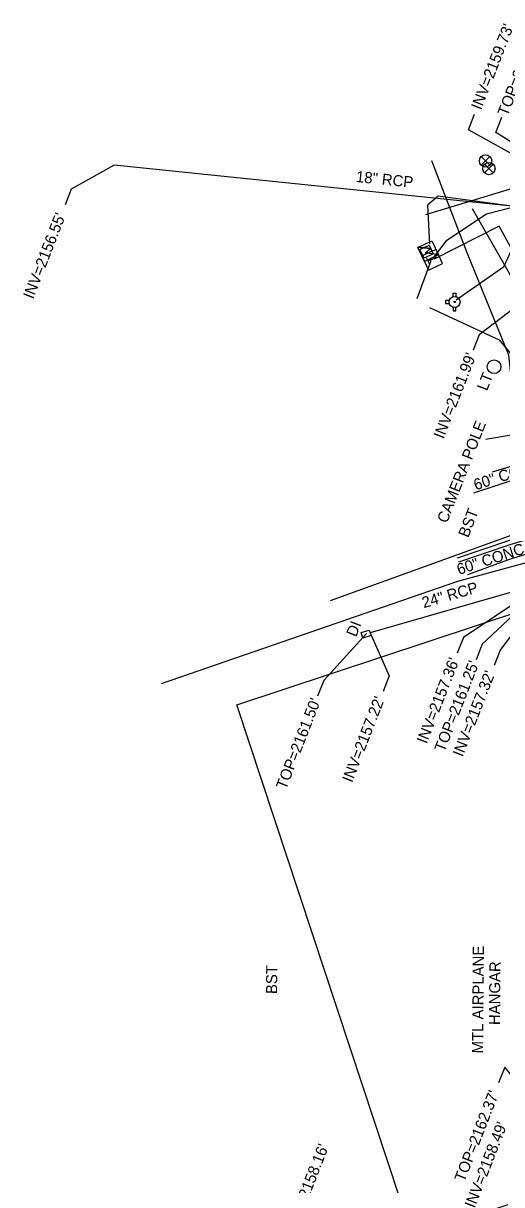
# Model space of a CAD drawing. Extents: x 945964 to 948456, y 631061 to 636061.
# Drawn here: x 946200.3 to 946372.2, y 633199.7 to 633616.6 of the extents above; entities that cross this region are included whole.
import ezdxf

# ---------------------------------------------------------------- set-up
doc = ezdxf.new("R2010")
doc.units = 0
for name, color, linetype in [('Exist Building', 7, 'Continuous'), ('Exist Building Text', 7, 'Continuous'), ('Exist Roads Curbs', 7, 'Continuous'), ('Exist Roads EOP', 7, 'Continuous'), ('Exist Roads EOP Other', 7, 'Continuous'), ('Exist Roads EOP Other Text', 7, 'Continuous'), ('Exist Roads EOP Text', 7, 'Continuous'), ('Exist Structure Minor Catch Basin Top Elevation', 7, 'Continuous'), ('Exist Structure Minor Drop Inlet', 7, 'Continuous'), ('Exist Structure Minor Drop Inlet Text', 7, 'Continuous'), ('Exist Structure Minor Drop Inlet Top Elevation', 7, 'Continuous'), ('Exist Structure Minor Pipes RCP 18 Inch', 7, 'Continuous'), ('Exist Structure Minor Pipes RCP 18 Inch Invert', 7, 'Continuous'), ('Exist Structure Minor Pipes RCP 18 Inch Text', 7, 'Continuous'), ('Exist Structure Minor Pipes RCP 24 Inch', 7, 'Continuous'), ('Exist Structure Minor Pipes RCP 24 Inch Invert', 7, 'Continuous'), ('Exist Structure Minor Pipes RCP 24 Inch Text', 7, 'Continuous'), ('Exist Utilities Gas UG Line SUE', 7, 'Continuous'), ('Exist Utilities Other Located Object Leader', 7, 'Continuous'), ('Exist Utilities Other Located Object Text', 7, 'Continuous'), ('Exist Utilities Other Pole CELL', 7, 'Continuous'), ('Exist Utilities Other Pole Text', 7, 'Continuous'), ('Exist Utilities Power Transformer CELL', 7, 'Continuous'), ('Exist Utilities Power UG Cable SUE', 7, 'Continuous'), ('Exist Utilities Telephone Pedestal CELL', 7, 'Continuous'), ('Exist Utilities Telephone UG Cable SUE', 7, 'Continuous'), ('Exist Utilities Telephone UG FO SUE', 7, 'Continuous'), ('Exist Utilities Water Fire Hydrant CELL', 7, 'Continuous'), ('Exist Utilities Water UG Line SUE', 7, 'Continuous'), ('Exist Utilities Water Valve CELL', 7, 'Continuous')]:
    doc.layers.add(name, color=color, linetype=linetype)

# ---------------------------------------------------------------- blocks, each defined once
blk = doc.blocks.new('EXIST UTILITIES TELEPHONE PEDESTAL')
at = {"layer": 'Exist Utilities Telephone Pedestal CELL'}
blk.add_line((0, 0), (0, 0), dxfattribs=at)
blk.add_lwpolyline([(-0.0545, -0.0565), (0.0574, -0.0565), (0.0574, 0.0554), (-0.0545, 0.0554), (-0.0545, -0.0565)], dxfattribs=at)
blk.add_text('T', height=0.0684, dxfattribs=at).set_placement((-0.0226, -0.0343))
blk = doc.blocks.new('EXIST UTILITIES POWER TRANSFORMER')
at = {"layer": 'Exist Utilities Power Transformer CELL'}
blk.add_line((0, 0), (0, 0), dxfattribs=at)
blk.add_lwpolyline([(-0.0569, 0.0522), (0.0542, 0.0522), (0.0542, -0.0588), (-0.0569, -0.0588)], close=True, dxfattribs=at)
for points in [[(-0.0569, -0.0588), (-0.004, 0.0201), (0.0086, -0.0241), (0.0542, 0.0522)], [(-0.0555, -0.0588), (-0.004, 0.0159), (0.0077, -0.0278), (0.0542, 0.0491)]]:
    blk.add_lwpolyline(points, dxfattribs=at)
blk = doc.blocks.new('EXIST UTILITIES WATER VALVE')
at = {"layer": 'Exist Utilities Water Valve CELL'}
blk.add_lwpolyline([(0.0315, 0.0315), (-0.0315, -0.0315), (0, 0), (0.0315, -0.0315), (-0.0315, 0.0315)], dxfattribs=at)
blk.add_circle((0, 0), 0.0445, dxfattribs=at)
blk = doc.blocks.new('EXIST UTILITIES WATER FIRE HYDRANT')
at = {"layer": 'Exist Utilities Water Fire Hydrant CELL'}
blk.add_line((0, 0), (0, 0), dxfattribs=at)
for points in [[(-0.0382, 0.0103), (-0.064, 0.0103), (-0.064, -0.0103), (-0.0382, -0.0103)], [(-0.0103, 0.0382), (-0.0103, 0.064), (0.0103, 0.064), (0.0103, 0.0377)], [(-0.0103, -0.0382), (-0.0103, -0.064), (0.0103, -0.064), (0.0103, -0.0377)]]:
    blk.add_lwpolyline(points, dxfattribs=at)
for radius in [0.0395, 0.00485]:
    blk.add_circle((0, 0), radius, dxfattribs=at)
blk = doc.blocks.new('EXIST UTILITIES OTHER POLE')
at = {"layer": 'Exist Utilities Other Pole CELL'}
blk.add_circle((0, 0), 0.0493, dxfattribs=at)

msp = doc.modelspace()

# ---------------------------------------------------------------- linework, layer by layer
at = {"layer": 'Exist Building'}
msp.add_lwpolyline([(946443.69, 633215.47), (946340.12, 633181.14), (946277.06, 633372.05), (946380.49, 633406.21)], close=True, dxfattribs=at)
at = {"layer": 'Exist Roads Curbs'}
msp.add_lwpolyline([(946356.79, 633423.33), (946375.2, 633429.5), (946385.96, 633432.76), (946390.43, 633433.32), (946393.92, 633433.06), (946397.24, 633432.41), (946398.56, 633432.01)], dxfattribs=at)
at = {"layer": 'Exist Roads EOP'}
for points in [[(946395.61, 633473.47), (946397.09, 633469.17), (946397.19, 633466.43), (946396.51, 633463.92), (946395.02, 633461.81), (946393.17, 633459.77), (946390.62, 633457.89), (946388.03, 633456.47), (946378.82, 633453.47), (946361.95, 633447.99)], [(946356.32, 633424.75), (946374.75, 633430.93), (946385.65, 633434.23), (946390.39, 633434.82), (946394.12, 633434.55), (946397.6, 633433.87), (946402.55, 633432.35), (946408.59, 633429.59), (946414.48, 633425.92), (946418.03, 633423.03), (946423.58, 633417.87), (946427.76, 633412.39), (946431.85, 633405.16), (946434.62, 633399.21), (946437.11, 633392.39), (946440.04, 633382.71), (946444.03, 633370.06), (946449.76, 633351.25), (946456.69, 633328.4), (946462.97, 633307.72), (946467.95, 633291.29)]]:
    msp.add_lwpolyline(points, dxfattribs=at)
at = {"layer": 'Exist Roads EOP Other'}
for points in [[(946344.29, 633532.36), (946342.79, 633535.37), (946346.05, 633536.99), (946347.51, 633533.84), (946344.29, 633532.36)], [(946386.37, 633475.81), (946389.06, 633470.96), (946390.23, 633467.47), (946390.32, 633466.02), (946389.67, 633464.07), (946388.41, 633462.88), (946387.03, 633461.51), (946385.91, 633460.99), (946381.78, 633459.62), (946373.82, 633457), (946368.7, 633455.45)], [(946397.66, 633421.53), (946395.55, 633426.42), (946391.11, 633426.9), (946386.38, 633426.81), (946380.86, 633425.91), (946375.58, 633424.35), (946359.88, 633418.66)]]:
    msp.add_lwpolyline(points, dxfattribs=at)
at = {"layer": 'Exist Structure Minor Catch Basin Top Elevation'}
msp.add_lwpolyline([(946411.5, 633195.51), (946373.23, 633241.96), (946371.04, 633236.37)], dxfattribs=at)
at = {"layer": 'Exist Structure Minor Drop Inlet'}
msp.add_lwpolyline([(946324.59, 633398.78), (946325.26, 633396.85), (946322.31, 633395.97), (946321.7, 633398.01), (946324.59, 633398.78)], dxfattribs=at)
at = {"layer": 'Exist Structure Minor Drop Inlet Top Elevation'}
for points in [[(946418.35, 633547.12), (946370.03, 633577.37), (946372.21, 633582.95)], [(946389.17, 633416.22), (946365.15, 633393.74), (946362.97, 633388.16)], [(946323.63, 633397.55), (946308.22, 633380.71), (946306.03, 633375.12)]]:
    msp.add_lwpolyline(points, dxfattribs=at)
at = {"layer": 'Exist Structure Minor Pipes RCP 18 Inch'}
msp.add_line((946417.02, 633546.75), (946232.99, 633565.65), dxfattribs=at)
msp.add_line((946417.02, 633546.75), (946232.99, 633565.65), dxfattribs=at)
at = {"layer": 'Exist Structure Minor Pipes RCP 18 Inch Invert'}
for points in [[(946417.02, 633546.75), (946360.22, 633578.39), (946362.41, 633583.98)], [(946232.99, 633565.65), (946217.51, 633557.05), (946215.32, 633551.47)], [(946418.32, 633546.11), (946364.04, 633504.84), (946361.85, 633499.25)]]:
    msp.add_lwpolyline(points, dxfattribs=at)
at = {"layer": 'Exist Structure Minor Pipes RCP 24 Inch'}
msp.add_line((946387.98, 633415.96), (946324.86, 633397.79), dxfattribs=at)
at = {"layer": 'Exist Structure Minor Pipes RCP 24 Inch Invert'}
for points in [[(946387.98, 633415.96), (946358.38, 633396.16), (946356.19, 633390.57)], [(946389.55, 633415.66), (946371.57, 633391.67), (946369.38, 633386.08)], [(946324.86, 633397.79), (946331.78, 633382.43), (946329.6, 633376.84)]]:
    msp.add_lwpolyline(points, dxfattribs=at)
at = {"layer": 'Exist Utilities Gas UG Line SUE'}
msp.add_line((946310.62, 633409.44), (946417.38, 633448.02), dxfattribs=at)
for points in [[(946619.67, 632824.44), (946594.97, 632905.61), (946571.92, 632968.94), (946532.75, 633083.03), (946501.7, 633172.99), (946488.79, 633216.05), (946469.59, 633278.14), (946458.18, 633325.93), (946447.15, 633359.21), (946427.01, 633420.51), (946410.77, 633466.26), (946393.83, 633493.79), (946361.71, 633549.95)], [(946346.24, 633514.61), (946371.27, 633503.04), (946385.56, 633485.67), (946410.45, 633466.34)]]:
    msp.add_lwpolyline(points, dxfattribs=at)
at = {"layer": 'Exist Utilities Other Located Object Leader'}
msp.add_lwpolyline([(946381.08, 633469.74), (946366.41, 633467.27)], dxfattribs=at)
at = {"layer": 'Exist Utilities Power UG Cable SUE'}
msp.add_lwpolyline([(946485.31, 633431.45), (946479.38, 633442.7), (946463.36, 633488.11), (946452.17, 633505.48), (946414.56, 633545.7), (946349.36, 633554.61), (946345.45, 633551.29), (946346.17, 633537.3)], dxfattribs=at)
at = {"layer": 'Exist Utilities Telephone UG Cable SUE'}
msp.add_line((946346.7, 633531.33), (946341.66, 633517.76), dxfattribs=at)
for points in [[(946416.51, 633555.47), (946393.78, 633548.5), (946375.09, 633550.21), (946366.73, 633548.12), (946352.03, 633538.41), (946347.53, 633532.4)], [(946468.58, 633229.29), (946480.21, 633232.87), (946453.77, 633319.31), (946426.75, 633410.6), (946402.77, 633464), (946403.53, 633475.93), (946397.38, 633496.17), (946371.22, 633543.74), (946347.87, 633531.98)]]:
    msp.add_lwpolyline(points, dxfattribs=at)
at = {"layer": 'Exist Utilities Telephone UG FO SUE'}
msp.add_line((946405.56, 633566.23), (946344.81, 633547.82), dxfattribs=at)
for points in [[(946471.38, 633227.98), (946453.83, 633274.93), (946421.19, 633376.74), (946415.16, 633410.84), (946396.18, 633428.86), (946375.84, 633486.53), (946374.65, 633497.52), (946359.69, 633534.21), (946347.03, 633567.22)], [(946249.92, 633379.71), (946356.43, 633416.36), (946396.06, 633427.15)]]:
    msp.add_lwpolyline(points, dxfattribs=at)
at = {"layer": 'Exist Utilities Water UG Line SUE'}
msp.add_lwpolyline([(946380.27, 633543), (946378.58, 633541.55), (946372.81, 633529.03), (946355.76, 633517.27)], dxfattribs=at)

# ---------------------------------------------------------------- block references
at = {"layer": 'Exist Utilities Other Pole CELL', "xscale": 50, "yscale": 50}
msp.add_blockref('EXIST UTILITIES OTHER POLE', (946369.38, 633493.33), dxfattribs=at)
at = {"layer": 'Exist Utilities Power Transformer CELL', "xscale": 49.99999999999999, "yscale": 49.999999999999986, "rotation": 115.10487278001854}
msp.add_blockref('EXIST UTILITIES POWER TRANSFORMER', (946345.53, 633534.78), dxfattribs=at)
at = {"layer": 'Exist Utilities Telephone Pedestal CELL', "xscale": 49.99999999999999, "yscale": 49.99999999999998, "rotation": 114.83996844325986}
msp.add_blockref('EXIST UTILITIES TELEPHONE PEDESTAL', (946347.19, 633531.66), dxfattribs=at)
at = {"layer": 'Exist Utilities Water Fire Hydrant CELL', "xscale": 50, "yscale": 50}
msp.add_blockref('EXIST UTILITIES WATER FIRE HYDRANT', (946355.2, 633516.59), dxfattribs=at)
at = {"layer": 'Exist Utilities Water Valve CELL', "xscale": 50, "yscale": 50}
for p in [(946366.35, 633567.2), (946367.55, 633564.46)]:
    msp.add_blockref('EXIST UTILITIES WATER VALVE', p, dxfattribs=at)

# ---------------------------------------------------------------- texts
at = {"layer": 'Exist Building Text'}
for s, p in [('MTL AIRPLANE', (946365.45, 633246.88)), ('HANGAR', (946371.53, 633257.05))]:
    msp.add_text(s, height=4, rotation=89.5187, dxfattribs=at).set_placement(p)
at = {"layer": 'Exist Roads EOP Other Text'}
for rotation, p in [(68.935, (946360.13, 633431.75)), (89.5187, (946291.48, 633268.18))]:
    msp.add_text('BST', height=4, rotation=rotation, dxfattribs=at).set_placement(p)
at = {"layer": 'Exist Roads EOP Text'}
for p in [(946362.82, 633448.95), (946356.78, 633418.58)]:
    msp.add_text('60" CONC', height=4, rotation=18.0277, dxfattribs=at).set_placement(p)
at = {"layer": 'Exist Structure Minor Catch Basin Top Elevation'}
msp.add_text("TOP=2162.37'", height=4, rotation=68.6189, dxfattribs=at).set_placement((946358.74, 633200.5))
at = {"layer": 'Exist Structure Minor Drop Inlet Text'}
msp.add_text('DI', height=4, rotation=68.619, dxfattribs=at).set_placement((946319.88, 633396.1))
at = {"layer": 'Exist Structure Minor Drop Inlet Top Elevation'}
for s, p in [("TOP=2167.02'", (946374.22, 633583)), ("TOP=2161.25'", (946351.54, 633354.77)), ("TOP=2161.50'", (946294.67, 633341.33))]:
    msp.add_text(s, height=4, rotation=68.6189, dxfattribs=at).set_placement(p)
at = {"layer": 'Exist Structure Minor Pipes RCP 18 Inch Invert'}
for s, p in [("INV=2159.73'", (946364.72, 633585.25)), ("INV=2156.55'", (946203.85, 633517.39)), ("INV=2161.99'", (946351.26, 633467.18)), ("INV=2158.49'", (946362.42, 633191.12)), ("INV=2158.16'", (946298.3, 633183.25))]:
    msp.add_text(s, height=4, rotation=68.6189, dxfattribs=at).set_placement(p)
at = {"layer": 'Exist Structure Minor Pipes RCP 18 Inch Text'}
msp.add_text('18" RCP', height=4, rotation=354.1362, dxfattribs=at).set_placement((946319.65, 633559.67))
at = {"layer": 'Exist Structure Minor Pipes RCP 24 Inch Invert'}
for s, p in [("INV=2157.36'", (946345.19, 633357.75)), ("INV=2157.32'", (946358.08, 633353.07)), ("INV=2157.22'", (946318.4, 633343.85))]:
    msp.add_text(s, height=4, rotation=68.6189, dxfattribs=at).set_placement(p)
at = {"layer": 'Exist Structure Minor Pipes RCP 24 Inch Text'}
msp.add_text('24" RCP', height=4, rotation=16.0609, dxfattribs=at).set_placement((946344.15, 633406.67))
at = {"layer": 'Exist Utilities Other Located Object Text'}
msp.add_text('CAMERA POLE', height=4, rotation=68.619, dxfattribs=at).set_placement((946352.5, 633436.94))
at = {"layer": 'Exist Utilities Other Pole Text'}
msp.add_text('LT', height=4, rotation=68.619, dxfattribs=at).set_placement((946366.86, 633484.43))

doc.saveas('drawing.dxf')
